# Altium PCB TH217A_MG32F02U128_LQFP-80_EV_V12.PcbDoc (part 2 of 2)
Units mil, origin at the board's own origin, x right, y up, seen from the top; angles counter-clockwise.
Board outline 4606.3 x 2637.8 mil, 2 copper layers (Top Layer, Bottom Layer); 131 components, 143 nets, 610 pads, 279 vias.
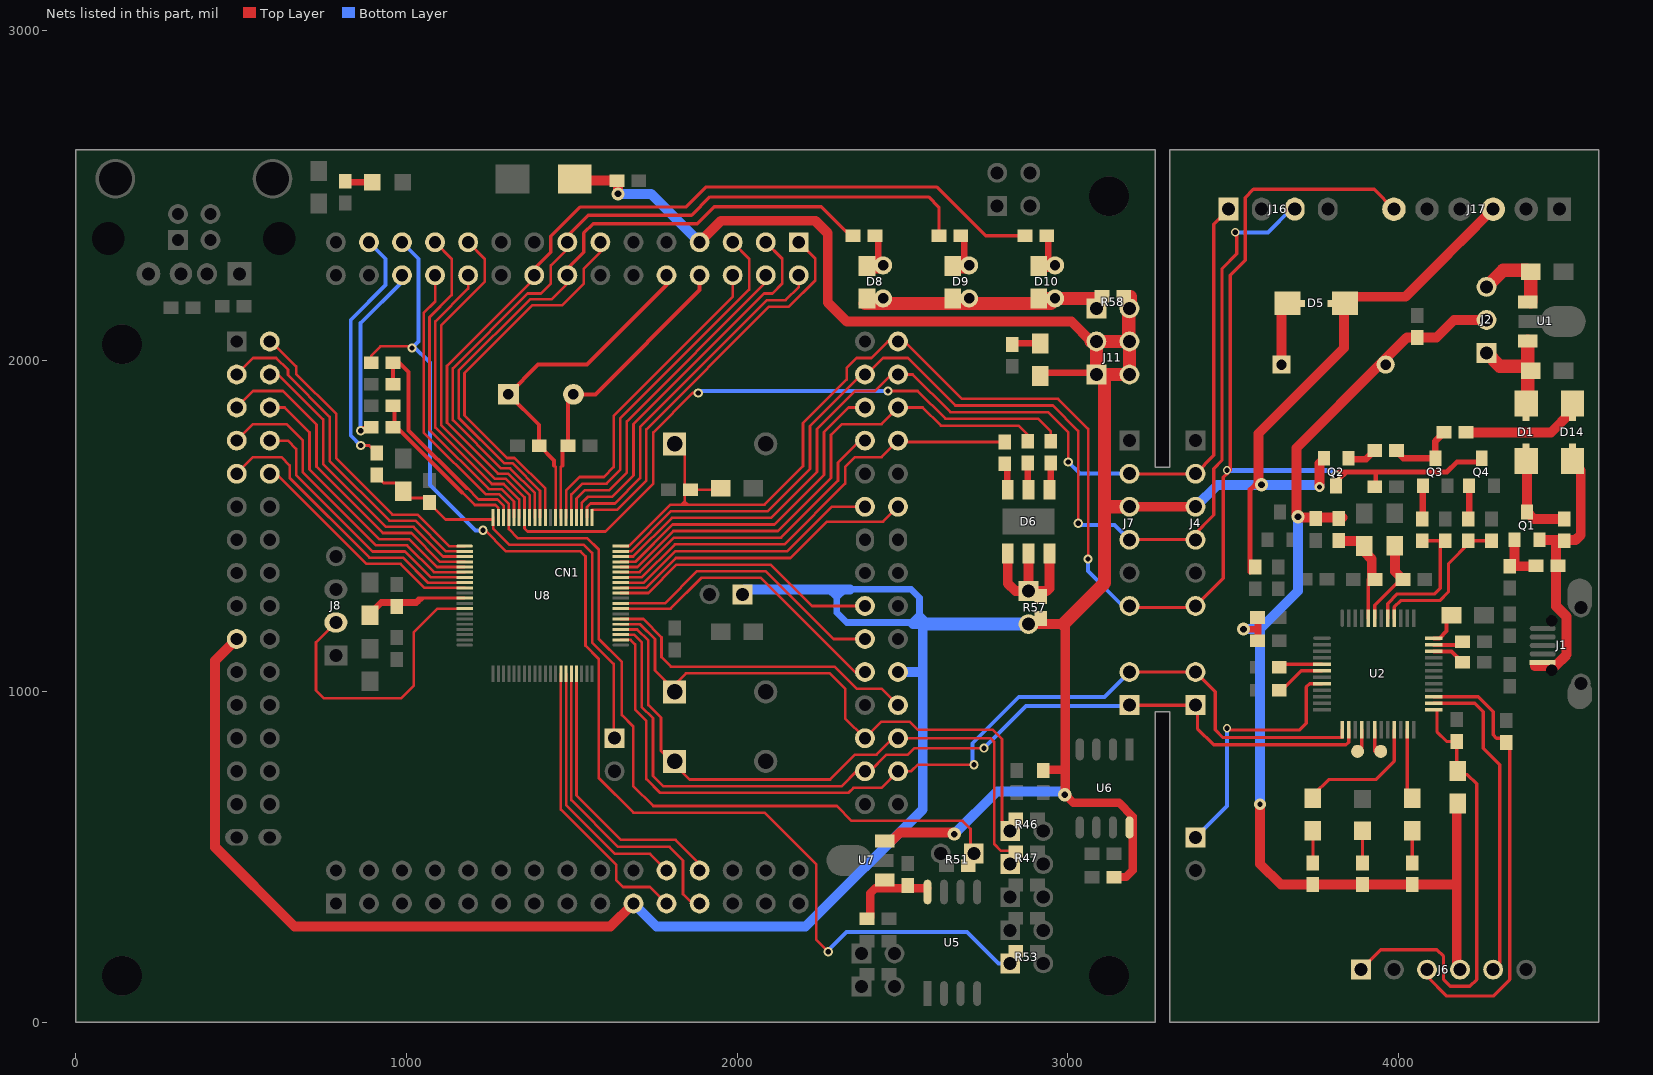
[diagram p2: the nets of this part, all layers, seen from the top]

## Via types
v1: diameter 20, hole 12, Top Layer to Bottom Layer, tented both sides, 126 vias
v2: diameter 30, hole 12, Top Layer to Bottom Layer, tented both sides, 95 vias
v3: diameter 25, hole 12, Top Layer to Bottom Layer, tented both sides, 32 vias
v4: diameter 28, hole 16, Top Layer to Bottom Layer, tented both sides, 12 vias
v5: diameter 40, hole 20, Top Layer to Bottom Layer, tented both sides, 6 vias
v6: diameter 25, hole 16, Top Layer to Bottom Layer, tented both sides, 4 vias
v7: diameter 30, hole 16, Top Layer to Bottom Layer, tented both sides, 2 vias
v8: diameter 50, hole 12, Top Layer to Bottom Layer, tented both sides, 1 vias
v9: diameter 35, hole 16, Top Layer to Bottom Layer, tented both sides, 1 vias

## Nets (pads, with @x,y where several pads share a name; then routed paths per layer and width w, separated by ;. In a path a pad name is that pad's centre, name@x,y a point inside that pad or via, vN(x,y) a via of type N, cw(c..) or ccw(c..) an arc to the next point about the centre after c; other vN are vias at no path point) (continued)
MG_PB8(TX): CN1.33 J5.2 J15.2 U2.13 U8.22 | length 3001.1
  Top Layer w8: U8.22@1648.46,1156.1 1677.67,1156.1 1691.85,1141.93 1691.85,945.46 1725.91,911.39 1725.91,734.68 1766.85,693.74 2336.85,693.74 2351.85,708.74 2436.85,708.74 CN1.33@2486.85,758.74 2526.85,758.74 2546.85,778.74 v4(2716.85,778.74)
  Top Layer w10: J15.2@3186.85,1058.74 J5.2@3386.85,1058.74 3446.85,998.74 3446.85,883.74 3469.85,860.74 3761.85,860.74 ; 3721.85,860.74 3761.85,860.74 ; U2.13@3830.3,884.39 3830.3,860.74 3761.85,860.74
  Bottom Layer w12: v4(2716.85,778.74) 2711.85,783.74 2711.85,843.43 2852.17,983.74 3111.85,983.74 J15.2@3186.85,1058.74
MG_PB9(RX): CN1.34 J5.1 J15.1 U2.14 U8.23 | length 2918.8
  Top Layer w8: U8.23@1648.46,1171.85 1689.2,1171.85 1711.85,1149.2 1711.85,953.74 1745.91,919.68 1745.91,744.68 1776.85,713.74 2316.85,713.74 2361.85,758.74 CN1.34@2386.85,758.74 2401.85,758.74 2451.85,808.74 2516.85,808.74 2536.85,828.74 v4(2746.85,828.74)
  Top Layer w10: J15.1@3186.85,958.74 J5.1@3386.85,958.74 3392.62,952.97 3392.62,887.97 3441.85,838.74 3806.85,838.74 ; 3721.85,838.74 3806.85,838.74 ; U2.14@3849.99,884.39 3849.99,846.88 3841.85,838.74 3806.85,838.74
  Bottom Layer w12: v4(2746.85,828.74) 2873.57,955.46 J15.1@3183.57,955.46
MG_PB10: CN1.35 R47.1 SW3.1 U8.24 | length 1946.9
  Top Layer w8: U8.24@1648.46,1187.6 1697.99,1187.6 1731.85,1153.74 1731.85,958.74 1770,920.59 1770,820 SW3.1@1806.26,783.74 ; SW3.1@1801.26,788.74 SW3.1@1806.26,783.74 ; R47.1@2853.22,518.74 2843.22,518.74 2797.26,518.74 2778,538 2778,847.59 2766.85,858.74 CN1.35@2486.85,858.74 2471.85,858.74 2421.85,808.74 2356.85,808.74 2281.85,733.74 1856.26,733.74 SW3.1@1806.26,783.74
MG_PB11: CN1.36 R46.1 SW4.1 U8.25 | length 1770.1
  Top Layer w8: U8.25@1648.46,1203.35 1707.24,1203.35 1751.85,1158.74 1751.85,1063.74 SW4.1@1802.95,1012.64 ; SW4.1@1799.06,1008.74 1800.16,1009.84 1845.32,1055 2280.59,1055 2326.85,1008.74 2326.85,918.74 CN1.36@2386.85,858.74 2436.85,908.74 2521.85,908.74 2546.85,883.74 2774,883.74 2801.28,856.46 2801.28,609.31 2816.85,593.74 R46.1@2816.85,597.8 ; R46.1@2836.22,587.8 R46.1@2836.22,597.8
MG_PB12: CN1.37 U8.26 | length 981.4
  Top Layer w8: U8.26@1648.46,1219.1 1716.5,1219.09 1771.85,1163.74 1771.85,1103.74 1800.59,1075 2295.59,1075 2361.85,1008.74 2436.85,1008.74 CN1.37@2486.85,958.74
MG_PB13: CN1.40 U8.28 | length 895
  Top Layer w8: U8.28@1648.46,1250.59 1798.7,1250.59 1891.85,1343.74 2071.85,1343.74 2356.85,1058.74 CN1.40@2386.85,1058.74
MG_PB14: CN1.42 U8.29 | length 863.6
  Top Layer w8: U8.29@1648.46,1266.34 1782.18,1266.34 1879.58,1363.74 2086.85,1363.74 2291.85,1158.74 CN1.42@2386.85,1158.74
MG_PB15: CN1.44 U8.31 | length 825.7
  Top Layer w8: U8.31@1648.46,1297.84 1731.77,1297.83 1817.68,1383.74 2101.85,1383.74 2226.85,1258.74 CN1.44@2386.85,1258.74
MG_PC0: CN1.53 R28.1 U8.34 | length 1357.6
  Top Layer w8: U8.34@1648.46,1345.08 1711.82,1345.08 1811.94,1445.2 2143.31,1445.2 2326.85,1628.74 2326.85,1678.74 2356.85,1708.74 2436.85,1708.74 CN1.53@2486.85,1758.74 ; CN1.53@2490.85,1754.74 R28.1@2809.41,1754.74
MG_PC1: CN1.54 U8.35 | length 935.4
  Top Layer w8: U8.35@1648.46,1360.83 1705.29,1360.83 1809.67,1465.2 2133.31,1465.2 2305.64,1637.53 2305.64,1692.53 2371.85,1758.74 CN1.54@2386.85,1758.74
MG_PC2: CN1.55 R29.1 U8.36 | length 1560.4
  Top Layer w8: U8.36@1648.46,1376.58 1698.77,1376.57 1807.39,1485.2 2123.31,1485.2 2284.42,1646.31 2284.42,1776.16 2317.01,1808.74 2436.85,1808.74 CN1.55@2486.85,1858.74 2561.26,1858.74 2616.26,1803.74 2851.85,1803.74 2879.41,1776.18 R29.1@2879.41,1756.74
MG_PC3: CN1.56 U8.37 | length 1007.6
  Top Layer w8: U8.37@1648.46,1392.32 1692.25,1392.32 1805.12,1505.2 2113.31,1505.2 2263.21,1655.1 2263.21,1784.94 2337.01,1858.74 CN1.56@2386.85,1858.74
MG_PC7: CN1.61 U8.41 | length 1188.8
  Top Layer w8: U8.41@1561.85,1550 1638.04,1550 1725.59,1637.55 1725.59,1792.48 2096.85,2163.74 2156.85,2163.74 2236.85,2243.74 2236.85,2308.74 CN1.61@2186.85,2358.74
MG_PC8: CN1.62 U8.42 | length 1074.1
  Top Layer w8: U8.42@1546.1,1526.18 1546.1,1557.99 1556.85,1568.74 1630.28,1568.74 1706.85,1645.31 1706.85,1800.24 2090.35,2183.74 2146.85,2183.74 2186.85,2223.74 CN1.62@2186.85,2258.74
MG_PC9: CN1.63 U8.43 | length 1162
  Top Layer w8: U8.43@1530.35,1526.18 1530.35,1570.53 1548.57,1588.74 1622,1588.74 1686.85,1653.59 1686.85,1808.53 2082.06,2203.74 2106.85,2203.74 2136.85,2233.74 2136.85,2308.74 CN1.63@2086.85,2358.74
MG_PC10: CN1.64 U8.44 | length 1012.6
  Top Layer w8: U8.44@1514.61,1526.18 1514.61,1583.06 1540.28,1608.74 1613.71,1608.74 1666.85,1661.88 1666.85,1816.81 2086.85,2236.81 CN1.64@2086.85,2258.74
MG_PC11: CN1.65 U8.45 | length 1119.1
  Top Layer w8: U8.45@1498.86,1526.18 1498.86,1595.6 1532,1628.74 1605.43,1628.74 1646.85,1670.16 1646.85,1825.1 2036.85,2215.1 2036.85,2308.74 CN1.65@1986.85,2358.74
MG_PC12: CN1.66 U8.46 | length 984.2
  Top Layer w8: U8.46@1483.11,1526.18 1483.11,1608.14 1523.71,1648.74 1597.14,1648.74 1626.85,1678.45 1626.85,1833.38 1986.85,2193.38 CN1.66@1986.85,2258.74
MG_PD0: CN1.81 R30.1 U8.54 | length 3016
  Top Layer w8: CN1.81@1186.85,2358.74 1236.85,2308.74 1236.85,2238.74 1105.29,2107.18 1105.29,1805.93 1267.99,1643.23 1300.99,1643.23 1357.13,1587.09 U8.54@1357.13,1526.18 1357.13,1493.46 1366.85,1483.74 1601.85,1483.74 1746.85,1628.74 1746.85,1783.74 1865.85,1902.74 v4(1882.85,1902.74) v4@1876.85,1908.74 ; v4(2456.85,1908.74) 2546.26,1908.74 2630,1825 2910.59,1825 2949.41,1786.18 R30.1@2949.41,1756.74
  Bottom Layer w12: v4@1888.85,1908.74 v4(2456.85,1908.74) v4@2450.85,1902.74
MG_PD1: CN1.82 U8.55 | length 899.7
  Top Layer w8: CN1.82@1186.85,2258.74 1186.85,2218.74 1087.61,2119.5 1087.61,1798.61 1258.74,1627.48 1294.47,1627.48 1341.38,1580.57 U8.55@1341.38,1526.18
MG_PD2: CN1.83 U8.56 | length 1009.4
  Top Layer w8: CN1.83@1086.85,2358.74 1136.85,2308.74 1136.85,2198.74 1069.93,2131.82 1069.93,1791.29 1249.49,1611.73 1287.94,1611.73 1325.63,1574.04 U8.56@1325.63,1526.18
MG_PD3: CN1.84 R51.1 U8.57 | length 3106.7
  Top Layer w8: CN1.84@1086.85,2258.74 1086.85,2178.74 1052.26,2144.15 1052.26,1783.96 1240.24,1595.98 1281.42,1595.98 1309.88,1567.52 U8.57@1309.88,1526.18 1309.88,1490.71 1336.85,1463.74 1546.85,1463.74 1581.85,1428.74 1581.85,1158.74 1651.85,1088.74 1651.85,928.89 1685.91,894.82 1685.91,714.68 1746.85,653.74 2301.85,653.74 2346.85,608.74 2681.85,608.74 2706.22,584.37 R51.1@2706.22,520
MG_PD4: CN1.85 R53.1 R62.2 | length 3862.5
  Top Layer w8: R62.2@893.85,1993.74 893.85,2015.74 921.85,2043.74 v4@1006.85,2043.74 ; v4@1231.75,1493.84 1234.77,1490.82 1301.85,1423.74 1526.85,1423.74 1541.85,1408.74 1541.85,1138.74 1581.85,1098.74 1581.85,738.15 1686.26,633.74 2083.26,633.74 2240,477 2240,249.02 v4(2276.22,212.8)
  Bottom Layer w12: CN1.85@986.85,2358.74 1036.85,2308.74 1036.85,2058.74 v4@1021.85,2043.74 ; v4@1011.85,2043.74 1016.85,2043.74 v4@1021.85,2043.74 ; v4@1235,1486.81 1231.75,1486.81 1209.29,1486.81 1071.22,1624.88 1071.22,1994.37 v4@1021.85,2043.74 ; v4@2273.72,215.3 2331.22,272.8 2696.22,272.8 2791.22,177.8 R53.1@2826.22,177.8 R53.1@2836.22,177.8
  other v4: 1231.75,1487.8 1016.85,2038.74
MG_PD4X: R62.1 R64.1 U8.58 | length 723.3
  Top Layer w8: 1182.69,1616.47 1218.64,1580.52 1275.7,1580.52 1294.13,1562.09 U8.58@1294.13,1526.18
  Top Layer w12: R64.1@959.22,1935 R64.1@959.85,1935 ; R62.1@959.22,1993.74 R62.1@959.22,2000 ; R64.1@959.85,1928.74 R64.1@959.85,1935 ; 1181.22,1615 1006.22,1790 1006.22,1966.3 978.78,1993.74 R62.1@959.85,1993.74 R64.1@959.85,1935
MG_PD5: CN1.86 R61.2 | length 567.9
  Top Layer w8: v4@860.85,1793.74 865.85,1798.74 R61.2@893.85,1798.74 ; CN1.86@976.22,2248.11 CN1.86@986.85,2258.74
  Bottom Layer w12: v4@860.85,1793.74 861.85,1793.74 861.85,2113.74 986.85,2238.74 CN1.86@986.85,2258.74
  other v4: 861.85,1788.74
MG_PD5X: R61.1 R63.1 U8.59 | length 532.3
  Top Layer w8: R61.1@964.22,1805 964.22,1802 968.76,1802 R61.1@973.8,1802 ; 1161.02,1610.2 1207.22,1564 1268.86,1564 1278.39,1554.48 U8.59@1278.39,1526.18
  Top Layer w12: R61.1@959.22,1811.54 R61.1@964.22,1806.54 ; R61.1@964.22,1805 R61.1@964.22,1806.54 ; R63.1@964.22,1860 R61.1@964.22,1806.54 ; 1168.49,1602.27 968.76,1802 965.94,1804.83 R61.1@964.22,1806.54
MG_PD6: CN1.87 R60.2 | length 749.2
  Top Layer w8: v4(861.85,1743.74) 887.26,1743.74 R60.2@910,1721
  Bottom Layer w12: v4(861.85,1743.74) 831.85,1773.74 831.85,2123.74 936.85,2228.74 936.85,2308.74 CN1.87@886.85,2358.74
MG_PD6X: C41.1 C42.1 J19.1 R60.1 U8.60 | length 1360.4
  Top Layer w8: R60.1@910,1652 931.61,1630.39 965.39,1630.39 C41.1@990,1605.79 C41.1@1010.79,1585 ; C41.1@990,1585 C41.1@1010.79,1585 ; C42.1@1060,1575 1064,1575 1068.5,1570.5 C42.1@1069,1570 ; C42.1@1070,1570 C42.1@1069,1570 ; C42.1@1070,1572 1057,1585 C41.1@1010.79,1585 ; U8.60@1262.64,1526.18 U8.60@1262.64,1520 ; 1626.85,888.74 1626.85,1083.74 1561.85,1148.74 1561.85,1418.74 1536.85,1443.74 1311.85,1443.74 1262.64,1492.95 U8.60@1262.64,1520 ; C42.1@1069,1570 1119,1520 U8.60@1262.64,1520
MG_PD7: CN1.92 U8.61 | length 937.5
  Top Layer w8: CN1.92@586.85,2058.74 591.26,2058.74 666.85,1983.15 666.85,1960.31 788.19,1838.97 788.19,1704.98 958.17,1535 1033.83,1535 1129.27,1439.57 U8.61@1176.02,1439.57
MG_PD8: CN1.93 U8.62 | length 1040.1
  Top Layer w8: CN1.93@486.85,1958.74 536.85,2008.74 606.26,2008.74 641.85,1973.15 641.85,1957.02 768.19,1830.68 768.19,1696.69 948.49,1516.4 1027.53,1516.4 1120.11,1423.82 U8.62@1176.02,1423.82
MG_PD9: CN1.94 U8.63 | length 975.4
  Top Layer w8: CN1.94@586.85,1958.74 611.85,1958.74 748.19,1822.4 ; 691.85,1878.74 748.19,1822.4 ; U8.63@1176.02,1408.07 1111.13,1408.07 1021.4,1497.8 938.8,1497.8 748.19,1688.41 748.19,1822.4
MG_PD10: CN1.95 U8.64 | length 998.3
  Top Layer w8: CN1.95@486.85,1858.74 536.85,1908.74 626.85,1908.74 728.19,1807.4 728.19,1680.13 929.12,1479.2 1015,1479.2 1101.88,1392.32 U8.64@1176.02,1392.32
MG_PD11: CN1.96 U8.65 | length 854.8
  Top Layer w8: CN1.96@586.85,1858.74 631.85,1858.74 706.85,1783.74 706.85,1671.29 917.54,1460.6 1008.42,1460.6 1092.44,1376.57 U8.65@1176.02,1376.58
MG_PD12: CN1.97 U8.66 | length 951.5
  Top Layer w8: CN1.97@486.85,1758.74 536.85,1808.74 636.85,1808.74 686.85,1758.74 686.85,1663 907.85,1442 1002.02,1442 1083.19,1360.83 U8.66@1176.02,1360.83
MG_PD13: CN1.98 U8.67 | length 806.8
  Top Layer w8: CN1.98@586.85,1758.74 641.85,1758.74 666.85,1733.74 666.85,1654.72 898.17,1423.4 995.62,1423.4 1073.94,1345.08 U8.67@1176.02,1345.08
MG_PD14: CN1.99 U8.68 | length 888.9
  Top Layer w8: CN1.99@486.85,1658.74 536.85,1708.74 621.85,1708.74 646.85,1683.74 646.85,1646.43 888.48,1404.8 989.22,1404.8 1064.69,1329.33 U8.68@1176.02,1329.33
MG_PD15: CN1.100 U8.69 | length 732.1
  Top Layer w8: CN1.100@586.85,1658.74 606.26,1658.74 878.8,1386.2 982.81,1386.2 1055.43,1313.58 U8.69@1176.02,1313.58
MG_PE0: CN1.21 U8.14 | length 875.3
  Top Layer w8: U8.14@1467.36,1053.74 1467.36,642.64 1635,475 1635,428.74 1655,408.74 1736.85,408.74 CN1.21@1786.85,358.74
MG_PE1: CN1.22 U8.15 | length 782.7
  Top Layer w8: U8.15@1483.11,1053.74 1483.11,656.89 1631.26,508.74 1736.85,508.74 CN1.22@1786.85,458.74
MG_PE2: CN1.23 U8.16 | length 959.7
  Top Layer w8: U8.16@1498.86,1053.74 1498.86,671.14 1640.05,529.95 1795.64,529.95 1836.85,488.74 1836.85,386.89 1865,358.74 CN1.23@1886.85,358.74
MG_PE3: CN1.24 U8.17 | length 846.2
  Top Layer w8: U8.17@1514.61,1053.74 1514.61,685.39 1648.83,551.17 1814.42,551.17 1886.85,478.74 CN1.24@1886.85,458.74
MG_PE8: CN1.49 U8.32 | length 939.9
  Top Layer w8: U8.32@1648.46,1313.58 1724.86,1313.58 1815.02,1403.74 2161.85,1403.74 2271.85,1513.74 2441.85,1513.74 CN1.49@2486.85,1558.74
MG_PE9: CN1.50 U8.33 | length 833.4
  Top Layer w8: U8.33@1648.46,1329.33 1718.34,1329.33 1812.75,1423.74 2151.85,1423.74 2286.85,1558.74 CN1.50@2386.85,1558.74
MG_PE12: CN1.73 U8.50 | length 1169.5
  Top Layer w8: U8.50@1420.12,1526.18 1420.12,1613.18 1327.08,1706.22 1305,1706.22 1176,1835.22 1176,1962.89 1381.5,2168.38 1471.5,2168.38 1536.85,2233.74 1536.85,2278.74 1586.85,2328.74 CN1.73@1586.85,2358.74
MG_PE13: CN1.76 R54.1 U8.51 | length 2061.9
  Top Layer w8: U8.51@1404.37,1526.18 1404.37,1606.66 1320.56,1690.47 1295.75,1690.47 1158.32,1827.9 1158.32,1970.21 1374.17,2186.06 1439.17,2186.06 1486.85,2233.74 CN1.76@1486.85,2258.74
  Top Layer w10: CN1.76@1486.85,2258.74 1486.85,2278.74 1536.85,2328.74 1536.85,2386.85 1565,2415 1879.85,2415 1930.48,2465.62 2254.97,2465.62 2329.35,2391.24 2350.85,2391.24 R54.1@2363.35,2391.24
MG_PE14: CN1.75 R55.1 U8.52 | length 2408
  Top Layer w8: U8.52@1388.62,1526.18 1388.62,1600.14 1314.03,1674.72 1286.5,1674.72 1140.64,1820.58 1140.64,1977.53 1366.85,2203.74 1406.85,2203.74 1436.85,2233.74 1436.85,2288.74 1486.85,2338.74 CN1.75@1486.85,2350
  Top Layer w10: CN1.75@1486.85,2350 CN1.75@1486.85,2358.74 1486.85,2376.85 1550,2440 1862.43,2440 1918.05,2495.62 2579.38,2495.62 2610.85,2464.15 R55.1@2610.85,2378.74
MG_PE15: CN1.78 R56.1 U8.53 | length 2797.8
  Top Layer w8: U8.53@1372.87,1526.18 1372.87,1593.61 1307.51,1658.98 1277.24,1658.98 1122.97,1813.25 1122.97,1984.86 1386.85,2248.74 CN1.78@1386.85,2258.74 CN1.78@1386.85,2278.74
  Top Layer w10: CN1.78@1386.85,2278.74 1436.85,2328.74 1436.85,2376.85 1525,2465 1845,2465 1905.62,2525.62 2116.85,2525.62 ; 2256.22,2525.62 2116.85,2525.62 ; R56.1@2870.85,2378.74 2751.85,2378.74 2604.97,2525.62 2116.85,2525.62
MG_VR0X: C15.1 C17.1 U8.71 | length 373.3
  Top Layer w9: 1024,1271 1035.09,1282.09 1045.2,1282.09 ; 1031.85,1268.74 1045.2,1282.09 ; 1035.31,1266.18 1051.22,1282.09 ; U8.71@1176.02,1282.09 1051.22,1282.09 ; 1045.2,1282.09 1051.22,1282.09
  Top Layer w20: C15.1@880,1225 887.89,1232.89 924,1269 971.22,1269 1030,1269 1035,1274
NetC2_2: C2.2 Q1.1 R5.2 | length 165
  Top Layer w30: R5.2@4336.85,1378.74 R5.2@4351.85,1378.74 ; Q1.1@4351.85,1458.74 R5.2@4351.85,1378.74 ; C2.2@4421.85,1378.74 4417,1378.74 R5.2@4351.85,1378.74
NetC6_1: C6.1 C7.2 R10.2 U2.44 | length 308.4
  Top Layer w11: U2.44@3909.04,1221.87 C7.2@3909.04,1338.74
  Top Layer w30: R10.2@3831.85,1455.74 3896.81,1455.74 C6.1@3896.81,1439.53 3896.81,1423.19 3919.85,1400.15 C7.2@3919.85,1338.74
NetC8_2: C8.2 C9.1 U2.43 | length 242.8
  Top Layer w11: U2.43@3928.73,1221.87 3928.73,1260.62 C8.2@3993.85,1325.74
  Top Layer w30: C9.1@3990,1440.79 3990,1362.59 C8.2@4013.85,1338.74
NetC11_1: C11.1 U2.36 | length 96.9
  Top Layer w12: U2.36@4107.31,1160.9 4124.01,1160.9 4145.83,1182.72 C11.1@4145.83,1225 ; C11.1@4176.95,1213.84 C11.1@4181.95,1218.84
NetD1_1: D1.1 Q1.3 R1.2 | length 260.1
  Top Layer w30: D1.1@4389.85,1697.13 Q1.3@4389.85,1542.68 4410.79,1521.74 R1.2@4486.85,1521.74
NetD2_1: D2.1 R6.2 | length 97
  Top Layer w10: R6.2@3741.85,481.74 D2.1@3741.85,578.74
NetD3_1: D3.1 R9.2 | length 97
  Top Layer w10: R9.2@4041.85,481.74 D3.1@4041.85,578.74
NetD4_1: D4.1 R11.2 | length 97
  Top Layer w10: R11.2@3891.85,481.74 D4.1@3891.85,578.74
NetD5_1: D5.1 SW1.1 | length 179.1
  Top Layer w30: SW1.1@3646.89,1988.74 D5.1@3646.89,2167.87
NetD6_1: D6.1 D6.3 D6.5 R57.1 | length 448.5
  Top Layer w30: D6.1@2818.86,1417.28 2818.86,1326.73 2841.85,1303.74 R57.1@2881.85,1303.74 ; D6.3@2881.85,1417.28 R57.1@2881.85,1303.74 ; D6.5@2944.84,1417.28 2944.84,1311.73 2936.85,1303.74 2918.7,1303.74 R57.1@2881.85,1303.74
NetD6_2: D6.2 R28.2 | length 78.5
  Top Layer w20: D6.2@2816.85,1610.2 R28.2@2816.85,1688.74
NetD6_4: D6.4 R29.2 | length 80.5
  Top Layer w20: D6.4@2879.41,1610.2 R29.2@2879.41,1690.74
NetD6_6: D6.6 R30.2 | length 80.5
  Top Layer w20: D6.6@2949.41,1610.2 R30.2@2949.41,1690.74
NetD7_2: D7.2 R31.2 | length 85
  Top Layer w20: R31.2@2831.85,2053.74 D7.2@2916.85,2053.74
NetD8_1: D8.1 D9.1 D10.1 R58.1 | length 747
  Top Layer w40: D8.1@2386.85,2173.74 2393.17,2173.74 2441.85,2173.74 2653.17,2173.74 2701.85,2173.74 2913.17,2173.74 D10.1@2950,2173.74 ; D10.1@2913.17,2188.74 D10.1@2961.85,2188.74 3086.85,2188.74 R58.1@3097,2188.74
NetD8_2: D8.2 R54.2 | length 138.7
  Top Layer w20: D8.2@2393.17,2273.74 D8.2@2441.85,2273.74 ; D8.2@2426.85,2288.74 R54.2@2426.85,2378.74
NetD9_2: D9.2 R55.2 | length 138.7
  Top Layer w20: D9.2@2653.17,2273.74 D9.2@2701.85,2273.74 ; D9.2@2686.85,2283.74 2686.85,2287.29 2686.85,2288.74 R55.2@2686.85,2373.74
NetD10_2: D10.2 R56.2 | length 148.7
  Top Layer w20: D10.2@2913.17,2278.74 D10.2@2941.85,2278.74 ; R56.2@2941.85,2368.74 2941.85,2288.74 2941.85,2287.29 D10.2@2941.85,2278.74 ; D10.2@2971.85,2278.74 2961.85,2278.74 D10.2@2941.85,2278.74
NetD12_1: D12.1 R59.2 | length 65
  Top Layer w20: 835,2540 D12.1@897,2540 D12.1@900,2540
NetD14_2: D14.2 R17.1 | length 348.7
  Top Layer w30: R17.1@4204.81,1783.74 4456.81,1783.74 ; 4461.81,1783.74 D14.2@4520.89,1842.81 ; D14.2@4509.96,1866.89 D14.2@4521.81,1866.89 ; D14.2@4515.89,1842.81 D14.2@4516.81,1843.74
NetQ2_1: Q2.1 R18.2 | length 89.8
  Top Layer w20: Q2.1@3849.81,1702.68 3902.79,1702.68 R18.2@3928.85,1728.74
NetQ3_1: Q3.1 R19.2 | length 101.1
  Top Layer w20: R19.2@4071.85,1521.74 4074.35,1524.24 Q3.1@4074.35,1621.77
NetQ3_3: Q3.3 R17.2 R18.1 | length 192.7
  Top Layer w20: R18.1@3999.85,1728.74 3999.85,1720.7 4014.84,1705.71 Q3.3@4112.35,1705.71 ; 4112.35,1728.74 4112.35,1757.28 R17.2@4138.81,1783.74
NetQ4_1: Q4.1 R23.2 | length 97.5
  Top Layer w20: R23.2@4214.35,1524.24 Q4.1@4214.35,1621.77
NetR15_1: R15.1 U2.35 | length 108.8
  Top Layer w12: U2.35@4107.31,1140.21 4136.85,1140.21 ; 4169.11,1140.21 4136.85,1140.21 ; R15.1@4183.85,1140.21 4136.85,1140.21
NetR16_1: R16.1 U2.34 | length 100.1
  Top Layer w12: U2.34@4107.31,1121.53 4161.06,1121.53 R16.1@4193.85,1088.74
NetTP1_1: TP1.1 U2.16 | length 97.8
  Top Layer w10: TP1.1@3889.36,818.74 U2.16@3889.36,884.39 3889.36,852.25
NetTP2_1: TP2.1 U2.18 | length 65.6
  Top Layer w10: TP2.1@3928.73,818.74 U2.18@3928.73,884.39
P44: J6.5 U2.26 | length 969
  Top Layer w10: U2.26@4107.31,964.05 4231.54,964.05 4256.85,938.74 4256.85,828.74 4306.85,778.74 4306.85,178.74 J6.5@4286.85,158.74
P45: J6.3 R25.1 U2.27 | length 1354.4
  Top Layer w10: J6.3@4086.85,158.74 4086.85,138.74 4146.85,78.74 4286.85,78.74 4336.85,128.74 4336.85,835.74 R25.1@4326.85,845.74 4313.85,858.74 4296.85,858.74 4286.85,868.74 4286.85,938.74 4241.86,983.73 U2.27@4107.31,983.73
PASS: D3.2 U2.23 | length 191.9
  Top Layer w10: D3.2@4027.15,692.47 U2.23@4027.15,884.39
RST: C12.2 J6.1 R22.2 U2.25 | length 1353.4
  Top Layer w10: J6.1@3886.85,158.74 3946.85,218.74 4116.85,218.74 4136.85,198.74 4136.85,128.74 4156.85,108.74 4216.85,108.74 4236.85,128.74 4236.85,720.64 4208.75,748.74 C12.2@4181.75,748.74 ; U2.25@4116.85,944.36 4116.85,878.74 4146.85,848.74 R22.2@4176.85,848.74 C12.2@4176.85,761.74
RST/MG_PC6: C13.2 CN1.59 J4.6 J7.6 J17.6 Q2.3 Q4.3 R21.1 R27.2 SW2.1 U8.40 | length 5977.4
  Top Layer w8: SW2.1@1841.75,1738.74 R27.2@1841.75,1618.74 ; R27.2@1857.78,1610 1859.22,1610 C13.2@1921.75,1610 ; R27.2@1859.22,1618.74 R27.2@1841.75,1618.74 ; v4(3061.85,1400.64) 3061.85,1793.86 2970.71,1885 2680,1885 2506.26,2058.74 CN1.59@2486.85,2058.74 2456.85,2058.74 2406.85,2008.74 2361.85,2008.74 2331.85,1978.74 2331.85,1943.58 2199.57,1811.3 2199.57,1681.46 2083.31,1565.2 1851.55,1565.2 ; U8.40@1672.68,1439.57 1798.31,1565.2 1831.95,1565.2 ; U8.40@1672.68,1439.57 U8.40@1648.46,1439.57 U8.40@1672.68,1439.57 ; 1831.95,1565.2 1841.75,1565.2 ; 1831.95,1565.2 1841.75,1575 ; 1841.75,1565.2 1841.75,1575 ; 1841.75,1565.2 1851.55,1565.2 ; 1841.75,1575 1841.75,1610.64 R27.2@1841.75,1618.74 ; 1841.75,1575 1851.55,1565.2
  Top Layer w10: J7.6@3186.85,1253.74 J4.6@3386.85,1253.74 ; J4.6@3386.85,1252.74 J4.6@3387.85,1252.74 ; J4.6@3386.85,1258.74 3470.6,1342.49 3470.6,1647.49 3486.85,1663.74 3491.85,1668.74 3491.85,1803.74 ; 3491.85,1913.74 3491.85,1803.74 ; 3491.85,2228.74 3491.85,2058.74 ; J17.6@3986.85,2458.74 3926.85,2518.74 3561.85,2518.74 3536.85,2493.74 3536.85,2303.74 3491.85,2258.74 3491.85,2058.74 ; 3491.85,1803.74 3491.85,2058.74
  Top Layer w15: Q2.3@3811.81,1633.74 Q2.3@3816.81,1638.74 ; v7(3811.81,1653.74) 3821.81,1663.74 3841.81,1663.74 ; Q2.3@3816.81,1613.74 3816.81,1621.77 Q2.3@3816.81,1638.74 ; v7@3816.81,1656.74 3816.81,1653.74 Q2.3@3816.81,1638.74 ; R21.1@3931.81,1620.74 3931.81,1663.74 ; Q4.3@4242.44,1693.74 4176.81,1693.74 4146.81,1663.74 3931.81,1663.74 ; Q2.3@3816.81,1638.74 3821.81,1643.74 3841.81,1663.74 ; 3841.81,1663.74 3931.81,1663.74
  Bottom Layer w12: v4@3061.75,1398.74 3061.75,1363.84 3176.85,1248.74 J7.6@3186.85,1238.74
  Bottom Layer w15: v6(3481.85,1668.74) 3796.81,1668.74 v7(3811.81,1653.74) v7@3801.81,1663.74
RST_CTRL_51: R19.1 R20.1 U2.41 | length 475.8
  Top Layer w10: U2.41@3968.1,1221.87 3968.1,1265.99 3997.11,1295 4110,1295 4126.85,1311.85 R20.1@4126.85,1455.74 ; 4111.85,1455.74 R19.1@4071.85,1455.74 R20.1@4126.85,1455.74 ; R20.1@4141.85,1455.74 R20.1@4126.85,1455.74
RST_CTRL_ARM: R23.1 R24.1 U2.40 | length 460.5
  Top Layer w10: U2.40@3987.78,1221.87 3987.78,1255.67 4007.11,1275 4125,1275 4151.85,1301.85 4151.85,1386.85 4216.3,1451.3 4220.74,1455.74 R24.1@4281.85,1455.74
SWCLK/MG_PC4: CN1.57 J4.2 J7.2 J16.1 U8.38 | length 3081.8
  Top Layer w8: U8.38@1648.46,1408.07 1685.72,1408.07 1802.85,1525.2 2103.31,1525.2 2242,1663.89 2242,1793.73 2357.01,1908.74 2416.85,1908.74 2466.85,1958.74 CN1.57@2486.85,1958.74 2531.49,1958.74 2645.24,1845 2940,1845 3001.85,1783.15 v4(3001.85,1693.74)
  Top Layer w10: J7.2@3186.85,1657.74 J4.2@3386.85,1657.74 ; J4.2@3386.85,1658.74 3441.85,1713.74 3441.85,2413.74 J16.1@3486.85,2458.74
  Bottom Layer w12: v4(3001.85,1693.74) 3036.85,1658.74 J7.2@3186.85,1658.74 J7.2@3171.85,1673.74
SWDIO/MG_PC5: CN1.58 J4.4 J7.4 J16.3 U8.39 | length 3652.7
  Top Layer w8: U8.39@1648.46,1423.82 1679.2,1423.82 1800.58,1545.2 2093.31,1545.2 2220.78,1672.67 2220.78,1802.52 2377.01,1958.74 CN1.58@2386.85,1958.74 2391.85,1958.74 2441.85,2008.74 2516.85,2008.74 2660.59,1865 2955.36,1865 3031.85,1788.51 v4(3031.85,1508.74) v4@3031.85,1503.74
  Top Layer w10: J7.4@3186.85,1459.74 J4.4@3372.85,1459.74 ; J4.4@3386.85,1458.74 3371.85,1458.74 J4.4@3372.85,1459.74 ; v6@3511.85,2388.74 3511.85,2323.74 3466.85,2278.74 3466.85,1698.74 3441.85,1673.74 3441.85,1533.74 3379.35,1471.24 3379.35,1466.24 J4.4@3372.85,1459.74
  Top Layer w12: J7.4@3185.2,1459.74 J7.4@3186.85,1459.74 ; J4.4@3372.85,1459.74 J4.4@3385.2,1459.74
  Bottom Layer w12: v4@3031.85,1503.74 3141.85,1503.74 J7.4@3186.85,1458.74 ; v6(3506.85,2388.74) 3606.22,2388.74 J16.3@3676.22,2458.74
TOOL_OPTION0: R2.1 U2.5 | length 123.2
  Top Layer w10: R2.1@3649.85,1073.74 3658.77,1082.66 U2.5@3769.33,1082.66
TOOL_OPTION1: R3.1 U2.6 | length 141.9
  Top Layer w10: R3.1@3649.85,1003.74 R3.1@3651.85,1003.74 ; R3.1@3651.85,1008.74 3706.08,1062.97 U2.6@3769.33,1062.97
USBOK: D2.2 U2.21 | length 377.6
  Top Layer w10: D2.2@3746.22,690 3789.96,733.74 3931.85,733.74 3987.78,789.67 U2.21@3987.78,884.39
VCC3: C20.1 R32.2 U5.8 U7.1 | length 251.3
  Top Layer w25: R32.2@2403.22,317.8 2403.22,389.8 2418.43,405 2446.22,405 2516.85,405 U5.8@2576.22,405
VCC_USB: C2.1 D14.1 J1.1 Q1.2 R1.1 | length 827.7
  Top Layer w30: 4413.5,1076.22 4436.85,1076.22 4464.41,1076.22 4474.29,1076.22 4509.29,1111.22 4509.29,1226.22 4479.29,1256.22 ; Q1.2@4426.85,1458.74 4501.85,1458.74 4536.81,1458.74 4551.81,1473.74 4551.81,1668.19 D14.1@4524.84,1695.16 ; 4476.73,1257.56 4476.73,1380 4476.73,1453.74
VCP_OPTION: J3.1 U2.8 | length 939.2
  Top Layer w10: v6@3481.85,883.74 3701.85,883.74 ; 3536.85,883.74 3701.85,883.74 ; U2.8@3769.33,1023.6 3731.71,1023.6 3721.85,1013.74 3721.85,903.74 3701.85,883.74
  Bottom Layer w12: J3.1@3386.85,558.74 3481.85,653.74 v6@3481.85,883.74
  other v6: 3481.85,888.74
VDD: C12.1 J2.2 J6.4 R4.1 R6.1 R9.1 R10.1 R11.1 R12.1 R13.1 R14.2 SW1.2 | length 3457.6
  Top Layer w20: v5(3531.85,1188.74) 3565.78,1188.74 ; R12.1@3575.85,1153.74 R13.1@3575.85,1223.3
  Top Layer w30: v9@3581.85,658.74 3581.85,478.74 3644.85,415.74 R6.1@3741.85,415.74 R11.1@3891.85,415.74 R9.1@4041.85,415.74 4176.85,415.74 ; v5@3691.81,1533.74 3691.81,1736.81 SW1.2@3952.8,1997.8 ; v5@3703.81,1526.74 3750,1526.74 R14.2@3751.81,1526.74 ; R14.2@3756.81,1526.74 3820,1526.74 R10.1@3831.85,1526.74 ; SW1.2@3955.3,1995.3 SW1.2@3960,2000 ; SW1.2@3955.3,2000.3 SW1.2@3952.8,1997.8 ; R4.1@4043.85,2070.74 R4.1@4056.85,2070.74 ; J6.4@4176.85,158.74 4176.85,415.74 ; C12.1@4176.85,660.79 4176.85,415.74 ; J2.2@4266.85,2123.74 4168.81,2123.74 4115.81,2070.74 R4.1@4056.85,2070.74 ; SW1.2@3952.8,1997.8 4025.74,2070.74 R4.1@4056.85,2070.74
  Bottom Layer w30: v5(3531.85,1188.74) 3581.85,1188.74 ; v9@3581.85,658.74 3581.85,1188.74 ; 3696.81,1303.7 3581.85,1188.74 ; 3696.81,1305 v5(3696.81,1528.74)
  other v9: 3581.75,658.74
VDD3: C5.1 J2.3 U1.1 | length 238.3
  Top Layer w40: J2.3@4266.85,2223.74 4316.85,2273.74 4388.81,2273.74 C5.1@4388.81,2270 ; U1.1@4400.79,2178.11 C5.1@4400.79,2270
VDD5: C4.1 D1.2 J2.1 U1.3 | length 301.2
  Top Layer w40: J2.1@4266.85,2023.74 4306.85,1983.74 C4.1@4391.81,1983.74 ; D1.2@4391.81,1900.35 4391.81,1970 C4.1@4391.81,1983.74 ; U1.3@4391.81,2060 C4.1@4391.81,1983.74
VDUT: C40.1 CN1.19 CN1.39 CN1.67 CN1.109 D5.2 D7.1 D11.2 J4.3 J7.3 J11.1 J11.2 J11.3 J11.4 J17.3 J18.1 Q2.2 R7.1 R44.1 R45.1 R57.2 R58.2 U6.8 U7.3 | length 12873.4
  Top Layer w15: R7.1@3551.85,1360.74 3551.85,1376.74 R7.1@3551.85,1395.74 ; R7.1@3573.85,1373.74 3568.85,1378.74 R7.1@3551.85,1395.74 ; v5@3581.22,1640 3576.85,1635.63 3576.22,1635 3551.85,1610.63 R7.1@3551.85,1395.74
  Top Layer w20: D7.1@2916.22,1963.74 2916.85,1963.74 3086.85,1963.74 J11.1@3111.85,1963.74
  Top Layer w25: R44.1@2926.22,763.24 2992.85,763.24 ; v5@2992.85,687.8 3016.91,663.74 3154.96,663.74 3196.85,621.85 3196.85,588.74 3196.85,458.74 3176.85,438.74 R45.1@3139.85,438.74
  Top Layer w30: CN1.109@486.85,1158.74 421.85,1093.74 421.85,528.74 661.85,288.74 1616.85,288.74 CN1.19@1686.85,358.74 ; D11.2@1525,2545 C40.1@1637,2545 ; v5(1640,2505) C40.1@1640,2545 ; CN1.67@1886.85,2358.74 1951.85,2423.74 2236.85,2423.74 2274.51,2386.08 2274.51,2176.08 2331.85,2118.74 3011.26,2118.74 J11.2@3071.26,2058.74 ; U7.3@2446.22,548.11 2467,548.11 2492.63,573.74 v5@2656.85,573.74 ; R57.2@2881.85,1203.74 2918.7,1203.74 2986.85,1203.74 ; v5@2992.85,687.8 2992.85,763.24 2992.85,1199.06 ; J7.3@3186.85,1558.74 J4.3@3386.85,1558.74 ; v5@3576.85,1625 3576.85,1635.63 3576.85,1780.1 3835.94,2039.19 3835.94,2173.74 3835.94,2193.74 3838.43,2193.74 4021.85,2193.74 J17.3@4286.85,2458.74 4186.85,2358.74 ; v7@3761.81,1619.24 3761.81,1689.68 Q2.2@3774.81,1702.68
  Top Layer w40: 2986.85,1203.74 3111.85,1328.74 3111.85,1558.74 ; J11.2@3071.26,2058.74 J11.2@3086.85,2058.74 ; J11.4@3185,2075 3185,2158.74 R58.2@3185,2179.26 ; J7.3@3186.85,1558.74 3111.85,1558.74 ; R58.2@3190,2158.15 3190,2158.74 R58.2@3190,2195 ; J11.2@3086.85,2058.74 J11.4@3186.85,2058.74 J11.3@3186.85,1958.74 J11.1@3111.85,1958.74 ; J11.2@3086.85,2058.74 3086.85,1963.74 J11.1@3086.85,1958.74 J11.1@3111.85,1958.74 ; 3111.85,1558.74 J11.1@3111.85,1958.74
  Bottom Layer w20: 2276.85,1308.74 2301.85,1283.74 ; 2301.85,1308.74 2301.85,1283.74 ; 2326.85,1308.74 2301.85,1283.74 ; 2341.85,1308.74 2526.85,1308.74 2551.85,1283.74 2551.85,1233.74 ; 2576.85,1208.74 2551.85,1233.74 ; 2301.85,1283.74 2301.85,1238.74 2331.85,1208.74 2526.85,1208.74 2551.85,1233.74
  Bottom Layer w30: v5(1640,2505) 1740.59,2505 CN1.67@1886.85,2358.74 ; CN1.19@1686.85,358.74 1756.85,288.74 2207.17,288.74 2561.85,643.43 2561.85,1058.74 ; J18.1@2021.85,1308.74 2276.85,1308.74 2301.85,1308.74 2326.85,1308.74 2341.85,1308.74 ; CN1.39@2486.85,1058.74 2561.85,1058.74 ; 2531.85,1203.74 2561.85,1203.74 ; 2546.85,1213.74 2561.85,1213.74 2561.85,1203.74 ; v5(2656.85,568.74) 2785.91,697.8 v5@2991.22,697.8 ; J4.3@3386.85,1558.74 3453.11,1625 v5(3586.22,1625) v7@3761.81,1625 ; 2561.85,1058.74 2561.85,1203.74
  Bottom Layer w40: 2561.85,1203.74 R57.2@2881.85,1203.74
  other v5: 2991.22,687.8
  other v7: 3761.81,1618.74
VREF+: J8.2 U8.73 | length 896.1
  Top Layer w8: J8.2@786.85,1208.74 726.85,1148.74 726.85,1003.15 750,980 985,980 1021.85,1016.85 1021.85,1178.74 1093.7,1250.59 U8.73@1176.02,1250.59
XIN/MG_PC13: C19.1 CN1.68 U8.47 X1.2 | length 945.3
  Top Layer w8: U8.47@1467.36,1526.18 1467.36,1678.74 1472.36,1683.74
  Top Layer w12: 1472.36,1683.74 1472.36,1727.25 C19.1@1488.85,1743.74 1488.85,1882.32 X1.2@1505.28,1898.74 1571.85,1898.74 1886.85,2213.74 CN1.68@1886.85,2258.74
XOUT/MG_PC14: C18.1 CN1.70 U8.48 X1.1 | length 1077
  Top Layer w8: 1446.61,1683.74 1451.61,1678.74 U8.48@1451.61,1526.18
  Top Layer w12: 1446.61,1683.74 1446.61,1698.98 C18.1@1401.85,1743.74 1401.85,1805.32 X1.1@1308.43,1898.74 1398.43,1988.74 1546.85,1988.74 1786.85,2228.74 CN1.70@1786.85,2258.74
pads on no net: CN1.1 CN1.15 CN1.16 CN1.18 CN1.20 CN1.25 CN1.26 CN1.30 CN1.31 CN1.38 CN1.43 CN1.45 CN1.46 CN1.47 CN1.48 CN1.51 CN1.52 CN1.60 CN1.71 CN1.72 CN1.74 CN1.77 CN1.79 CN1.80 CN1.88 CN1.89 CN1.90 CN1.91 CN1.101 CN1.102 CN1.103 CN1.104 CN1.105 CN1.106 CN1.108 CN1.110 CN1.111 CN1.112 CN1.113 CN1.121 CN1.122 D6.0 J1.0 J6.6 J7.1 J8.4 U2.1 U2.2 U2.3 U2.4 U2.7 U2.9 U2.10 U2.11 U2.12 U2.15 U2.17 U2.19 U2.20 U2.24 U2.28 U2.29 U2.30 U2.32 U2.37 U2.38 U2.39 U2.46

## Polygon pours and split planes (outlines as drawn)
GND_POWER on Top Layer "Top Layer-No Net" (hatched 90Degree grid 10 track 10, remove dead copper, pour order 1001): 17,28.74 4573.85,28.74 4573.85,2608.74 17,2608.74
GND_POWER on Bottom Layer "Top Layer-No Net" (hatched 90Degree grid 10 track 10, remove dead copper, pour order 1001): 20,28.74 4576.85,28.74 4576.85,2608.74 20,2608.74

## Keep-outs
Keep-Out Layer:
  circle w7.88: c3125.2,140 r122.58
  circle w7.88: c140,140 r122.58
  circle w7.88: c3125.2,2497.8 r122.58
  circle w7.88: c140,2050 r122.58

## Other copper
Top Layer:
  pour cut-out: 3226.85,2637.8 3346.85,2637.8 3346.85,-1.26 3226.85,-1.26
Bottom Layer:
  pour cut-out: 3226.85,2637.8 3346.85,2637.8 3346.85,-1.26 3226.85,-1.26

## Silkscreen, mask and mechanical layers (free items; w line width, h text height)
Top Overlay:
  circle w10: c3125.2,2497.8 r120
  circle w10: c140,2050 r120
  circle w10: c140,140 r120
  circle w10: c3125.2,140 r120
  lines w8: 890,2408.74 890,2445 ; 1000,2413.74 1045,2445 ; 1090,2408.74 1115,2440 ; 1190,2408.74 1190,2445 ; 1465.96,2464.04 1480.96,2464.04 1490,2455 1490,2408.74 ; 1575,2415 1575,2450 1589.04,2464.04
  lines w10: 700,1210 734.9,1210 ; 705,1350 736.85,1318.15
  lines w15: 1236.85,98.74 1236.85,718.74 ; 1236.85,98.74 236.85,98.74 236.85,1008.74 811.85,1008.74 811.85,718.74 1236.85,718.74 ; 1236.85,98.74 1436.85,98.74 1436.85,718.74 1236.85,718.74 ; 236.85,1608.74 846.22,1608.74 846.22,2040 1236.85,2040 1236.85,2398.74 1236.85,2637.8 236.85,2637.8 236.85,1608.74 ; 1736.85,98.74 1736.85,678.74 1936.85,678.74 1936.85,98.74 1736.85,98.74 ; 1736.85,1988.74 2156.85,1988.74 2156.85,1708.74 2706.85,1708.74 2706.85,2128.74 2261.85,2128.74 2261.85,2608.74 1936.85,2608.74 1936.85,2308.74 1736.85,2308.74 1736.85,1988.74 ; 2036.85,98.74 2036.85,678.74 2126.85,678.74 2126.85,1308.74 2436.85,1308.74 2436.85,1008.74 2736.85,1008.74 2736.85,583.74 2246.85,583.74 2246.85,98.74 2036.85,98.74
  text "GND" at 2591.85,2558.74 h50
  text "PD4" at 1090,2455 h50 r90
  text "PD2" at 1155,2455 h50 r90
  text "PD0" at 1220,2455 h50 r90
  text "PC7" at 2216.85,2448.74 h50 r90
  text "PD6" at 875,2435 h50
  text "GND" at 1825,2430 h50 r90
  text "VDUT" at 1906.85,2428.74 h50 r90
  text "PC11" at 2016.85,2428.74 h50 r90
  text "PC9" at 2116.85,2428.74 h50 r90
  text "PE12" at 1600,2425 h50
  text "PE14" at 1305,2420 h50
  text "When J16 Open," at 3361.85,2333.74 h45
  text "SCL" at 4406.85,2318.74 h35 r90
  text "CLK" at 4506.85,2318.74 h35 r90
  text "RST" at 4006.85,2308.74 h37 r90
  text "GND" at 4106.85,2303.74 h37 r90
  text "SDA" at 4206.85,2303.74 h37 r90
  text "VCC" at 4306.85,2303.74 h37 r90
  text "SW1 must be off." at 3361.85,2258.74 h45
  text "VDD3" at 4080,2205 h37
  text "PE13" at 2341.85,2158.74 h50 r90
  text "PE14" at 2601.85,2158.74 h50 r90
  text "PE15" at 2861.85,2158.74 h50 r90
  text "VDD" at 4110,2105 h37
  text "PD1" at 1205.66,2067.55 h50 r90
  text "PD5" at 1011.22,2060 h50 r90
  text "PD3" at 1111.22,2060 h50 r90
  text "PC8" at 2206.85,2058.74 h50 r90
  text "PC6" at 2556.85,2038.74 h50
  text "PD7" at 656.85,2028.74 h50
  text "PE15" at 1416.85,2018.74 h50 r90
  text "PE13" at 1516.85,2018.74 h50 r90
  text "PC14" at 1816.85,2018.74 h50 r90
  text "PC13" at 1906.85,2018.74 h50 r90
  text "PC12" at 2006.85,2018.74 h50 r90
  text "PC10" at 2106.85,2018.74 h50 r90
  text "VDD5" at 4080,1995 h37
  text "PD8" at 296.85,1938.74 h50
  text "PC5" at 2186.85,1938.74 h50
  text "PC4" at 2556.85,1938.74 h50
  text "PD9" at 656.85,1928.74 h50
  text "Power" at 2766.22,1872.8 h50
  text "VDUT" at 3041.75,1843.74 h50
  text "Power Off" at 3466.85,1843 h45
  text "Power On" at 3896.85,1843 h45
  text "PD10" at 261.73,1838.74 h50
  text "PC3" at 2186.85,1838.74 h50
  text "PC2" at 2556.85,1838.74 h50
  text "PD11" at 656.85,1828.74 h50
  text "PC1" at 2186.85,1738.74 h50
  text "PC0" at 2556.85,1738.74 h50
  text "PD12" at 256.85,1728.74 h50
  text "PD13" at 656.85,1728.74 h50
  text "RESET" at 1751.75,1675 h50 r90
  text "PD14" at 256.85,1628.74 h50
  text "PD15" at 656.85,1628.74 h50
  text "SCL" at 2996.85,1623.74 h45
  text "PE9" at 2186.85,1538.74 h50
  text "VDUT" at 2981.75,1533.74 h45
  text "PE8" at 2556.85,1528.74 h50
  text "U8 current" at 1806.94,1440.21 h45
  text "SDA" at 2996.85,1438.74 h45
  text "measurement" at 1806.85,1378.74 h45
  text "GND" at 720,1350 h50 r90
  text "GND" at 2996.85,1338.74 h45
  text "RST" at 2996.85,1238.74 h45
  text "GND" at 296.85,1228.74 h50
  text "PB15" at 2146.85,1228.74 h50
  text "VREF" at 700,1155 h50 r90
  text "PB14" at 2146.85,1128.74 h50
  text "GND" at 2556.85,1128.74 h50
  text "VDUT" at 256.85,1113.74 h50
  text "PB8_TX" at 2840,1075.64 h50
  text "↓" at 3506.85,1058.74 h110 r90
  text "↓" at 3116.85,1038.74 h110 r90
  text "PB13" at 2146.85,1028.74 h50
  text "VDUT" at 2556.85,1028.74 h50
  text "VDD" at 725,1025 h50 r90
  text "↓" at 3066.85,978.74 h110 r270
  text "↓" at 3456.85,958.74 h110 r270
  text "PB11" at 1754,936.59 h50 r90
  text "PA0" at 656.85,928.74 h50
  text "PB12" at 2556.85,928.74 h50
  text "PB9_RX" at 2841.75,885 h50
  text "PA2" at 656.85,838.74 h50
  text "PA1" at 306.85,828.74 h50
  text "PB11" at 2156.85,828.74 h50
  text "PB10" at 2556.85,828.74 h50
  text "TH217A_MG32F02U128" at 856.85,813.74 h38
  text "2021-05" at 1365,750 h33
  text "LQFP-80_EV_V12" at 856.85,748.74 h38
  text "PA4" at 656.85,738.74 h50
  text "PA3" at 286.85,728.74 h50
  text "PB9" at 2186.85,728.74 h50
  text "PB8" at 2556.85,728.74 h50
  text "PB10" at 1751.22,710 h50 r90
  text "PA6" at 656.85,638.74 h50
  text "PA5" at 286.85,628.74 h50
  text "PB7" at 2186.85,628.74 h50
  text "PA7" at 701.85,528.74 h50
  text "PB5" at 2106.85,528.74 h50 r90
  text "PA9" at 906.85,523.74 h50 r90
  text "PA11" at 1006.85,523.74 h50 r90
  text "PA13" at 1106.85,523.74 h50 r90
  text "PA15" at 1206.85,523.74 h50 r90
  text "PB1" at 1311.85,523.74 h50 r90
  text "PB3" at 1406.85,523.74 h50 r90
  text "PE1" at 1806.85,523.74 h50 r90
  text "PE3" at 1906.85,523.74 h50 r90
  text "J3 Open : Disable VCP." at 3339.85,318.74 h45
  text "J3 Short : Enable VCP." at 3334.85,233.74 h45
  text "PB0" at 1311.85,168.74 h50 r90
  text "GND" at 1616.85,168.74 h50 r90
  text "PE0" at 1816.85,168.74 h50 r90
  text "PE2" at 1906.85,168.74 h50 r90
  text "PB4" at 2116.85,168.74 h50 r90
  text "PB6" at 2226.85,168.74 h50 r90
  text "PA8" at 906.85,163.74 h50 r90
  text "PB2" at 1406.85,163.74 h50 r90
  text "VDUT" at 1711.85,124.45 h50 r90
  text "PA10" at 1006.85,123.74 h50 r90
  text "PA12" at 1106.85,123.74 h50 r90
  text "PA14" at 1206.85,123.74 h50 r90
Mechanical 1:
  circle w7.88: c3286.85,1613.74 r27
  circle w7.88: c3286.85,1503.74 r27
  circle w7.88: c3286.85,1416.74 r25
  circle w7.88: c3286.85,1298.74 r25
  circle w7.88: c3286.85,1008.74 r33
  lines w7.88: 3265.2,1078.74 3265.2,1232.74 3308.5,1232.74 3308.5,1078.74 3265.2,1078.74
  lines w8.88: 0,0 3265.2,0 3265.2,938.74 3308.5,938.74 3308.5,0 4606.3,0 4606.3,2637.8 3308.5,2637.8 3308.5,1678.74 3265.2,1678.74 3265.2,2637.8 0,2637.8 0,0
Mechanical 2:
  lines w6: 3286.85,1031.74 3286.85,1008.74 3309.85,1008.74 ; 3286.85,1321.74 3286.85,1298.74 3309.85,1298.74 ; 3286.85,1441.74 3286.85,1418.74 3309.85,1418.74 ; 3286.85,1526.74 3286.85,1503.74 3309.85,1503.74 ; 3286.85,1636.74 3286.85,1613.74 3309.85,1613.74
Drill Drawing:
  text ".Legend" at 4686.81,15 h40

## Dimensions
0,0 to 0,2637.8 on Top Overlay
0,0 to 4606.3,0 on Top Overlay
